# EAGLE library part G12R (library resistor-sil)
SIL RESISTOR
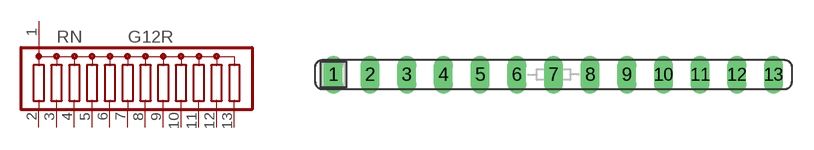
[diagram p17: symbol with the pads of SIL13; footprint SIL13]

Designator prefix RN

## G12R (OC_FARNELL: unknown; OC_NEWARK: unknown)  [SIL13]
1  1  pas
2  2  pas
3  3  pas
4  4  pas
5  5  pas
6  6  pas
7  7  pas
8  8  pas
9  9  pas
10  10  pas
11  11  pas
12  12  pas
13  13  pas

## Footprint SIL13 (pad centres in mm)
Single In Line
drill 0.813 long: 1 -15.24,0; 2 -12.7,0; 3 -10.16,0; 4 -7.62,0; 5 -5.08,0; 6 -2.54,0; 7 0,0; 8 2.54,0; 9 5.08,0; 10 7.62,0; 11 10.16,0; 12 12.7,0; 13 15.24,0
